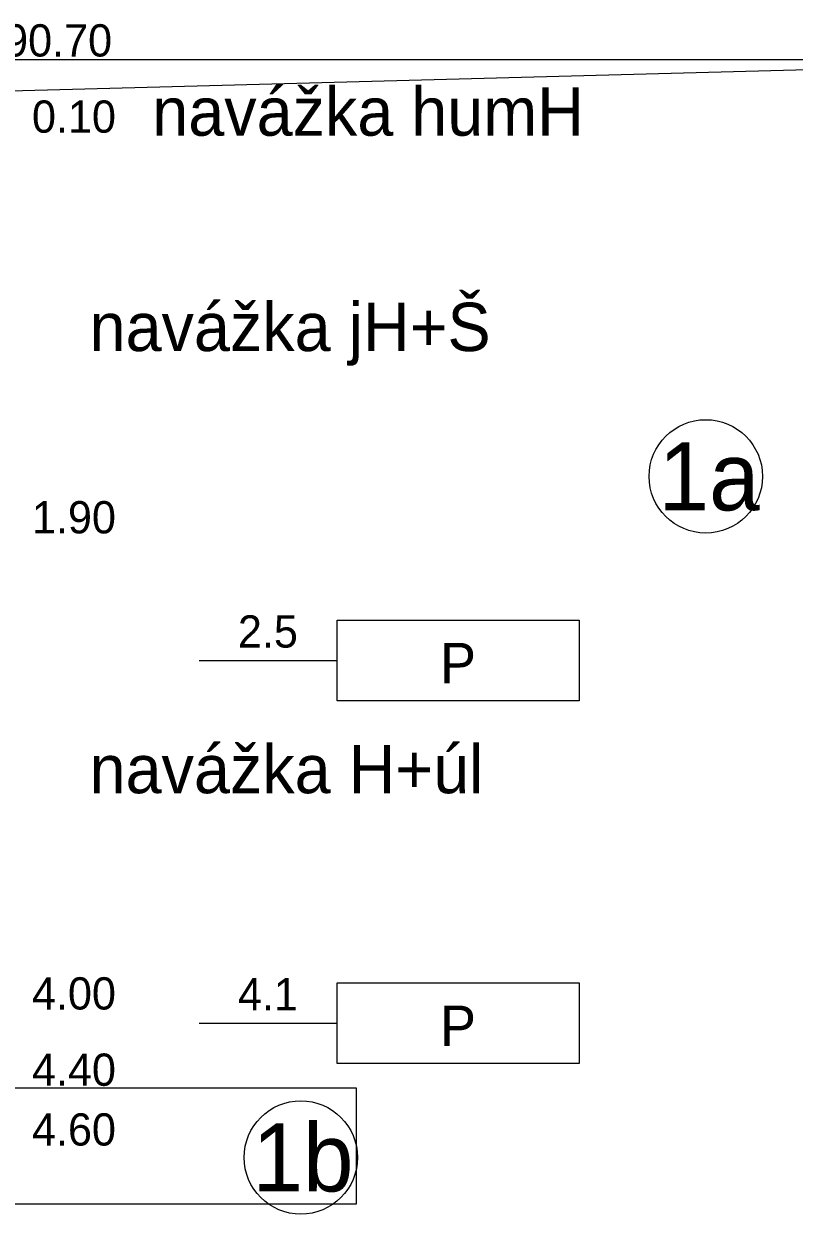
# Model space of a CAD drawing. Extents: x 3042 to 4120, y 576 to 2694.
# Drawn here: x 3219.67 to 3236.65, y 1423.95 to 1450.2 of the extents above; entities that cross this region are included whole.
import ezdxf

# ---------------------------------------------------------------- set-up
doc = ezdxf.new("R2010")
doc.units = 0
for name, color, linetype in [('11', 7, 'Continuous'), ('17', 7, 'Continuous'), ('52', 7, 'Continuous'), ('62', 7, 'Continuous'), ('pomocna', 7, 'Continuous'), ('rozhraní', 7, 'Continuous')]:
    doc.layers.add(name, color=color, linetype=linetype)

msp = doc.modelspace()

# ---------------------------------------------------------------- linework, layer by layer
at = {"layer": '11'}
msp.add_line((3217.182, 1448.664), (3269.032, 1450.064), dxfattribs=at)
at = {"layer": '62'}
for p, q in [((3223.532, 1436.164), (3226.58, 1436.164)), ((3223.532, 1428.164), (3226.58, 1428.164))]:
    msp.add_line(p, q, dxfattribs=at)
for points in [[(3231.914, 1435.275), (3226.58, 1435.275), (3226.58, 1437.053), (3231.914, 1437.053), (3231.914, 1435.275)], [(3231.914, 1427.275), (3226.58, 1427.275), (3226.58, 1429.053), (3231.914, 1429.053), (3231.914, 1427.275)]]:
    msp.add_lwpolyline(points, dxfattribs=at)
at = {"layer": 'pomocna'}
msp.add_line((3195.386, 1449.414), (3264.286, 1449.414), dxfattribs=at)
at = {"layer": 'rozhraní'}
msp.add_lwpolyline([(3210.014, 1426.742), (3226.993, 1426.742), (3226.993, 1424.174), (3210.014, 1424.174)], close=True, dxfattribs=at)
for centre in [(3234.703, 1440.223), (3225.776, 1425.203)]:
    msp.add_circle(centre, 1.25, dxfattribs=at)

# ---------------------------------------------------------------- texts
at = {"layer": '17'}
msp.add_text('190.70', height=0.7112, dxfattribs=at).set_placement((3218.706, 1449.482))
at = {"layer": '52'}
for s, height, p in [('navážka humH', 1.0668, (3222.501, 1447.736)), ('0.10', 0.7112, (3219.849, 1447.802)), ('navážka jH+Š', 1.0668, (3221.119, 1442.986)), ('1.90', 0.7112, (3219.849, 1438.966)), ('navážka H+úl', 1.0668, (3221.119, 1433.236)), ('4.00', 0.7112, (3219.849, 1428.466)), ('4.40', 0.7112, (3219.849, 1426.784)), ('4.60', 0.7112, (3219.849, 1425.466))]:
    msp.add_text(s, height=height, dxfattribs=at).set_placement(p)
at = {"layer": '62'}
for s, height, p in [('2.5', 0.7112, (3224.389, 1436.448)), ('P', 0.889, (3228.845, 1435.662)), ('4.1', 0.7112, (3224.389, 1428.448)), ('P', 0.889, (3228.845, 1427.662))]:
    msp.add_text(s, height=height, dxfattribs=at).set_placement(p)
at = {"layer": 'rozhraní'}
for s, p in [('1a', (3233.659, 1439.473)), ('1b', (3224.707, 1424.453))]:
    msp.add_text(s, height=1.5, dxfattribs=at).set_placement(p)

doc.saveas('drawing.dxf')
